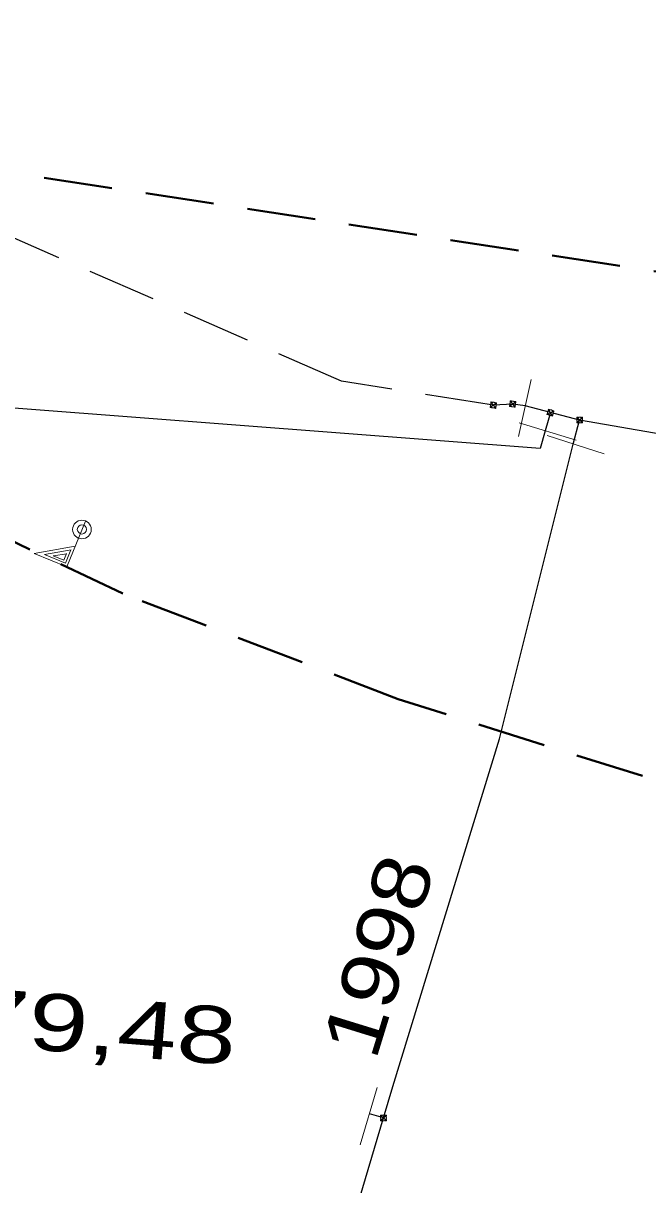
# Model space of a CAD drawing. Extents: x -740851 to -738888, y -1041382 to -1040235.
# Drawn here: x -739007.19 to -738996.26, y -1041347.67 to -1041327.35 of the extents above; entities that cross this region are included whole.
import ezdxf

# ---------------------------------------------------------------- set-up
doc = ezdxf.new("R2010")
doc.units = 0
doc.header["$LTSCALE"] = 0.4
doc.linetypes.add('MEDIUM_DASHED', pattern=[4.5, 3, -1.5])
doc.layers.add('18', color=7, linetype='Continuous', lineweight=13)
doc.layers.add('8', color=7, linetype='Continuous', lineweight=13)

msp = doc.modelspace()

# ---------------------------------------------------------------- linework, layer by layer
at = {"layer": '18', "linetype": 'MEDIUM_DASHED', "lineweight": 40}
msp.add_lwpolyline([(-738957.54, -1041347.45), (-738989.227, -1041342.273), (-738994.634, -1041341.058), (-739000.628, -1041339.172), (-739005.448, -1041337.328), (-739010.163, -1041335.083)], dxfattribs=at)
at = {"layer": '18'}
for points in [[(-739006.102, -1041336.058), (-739006.428, -1041336.858), (-739007, -1041336.626), (-739006.281, -1041336.497)], [(-739006.356, -1041336.56), (-739006.451, -1041336.794), (-739006.816, -1041336.645), (-739006.352, -1041336.562)], [(-739006.432, -1041336.627), (-739006.48, -1041336.744), (-739006.667, -1041336.668), (-739006.428, -1041336.629)]]:
    msp.add_lwpolyline(points, dxfattribs=at)
for centre, radius in [((-739006.163, -1041336.205), 0.163), ((-739006.163, -1041336.204), 0.0805)]:
    msp.add_circle(centre, radius, dxfattribs=at)
at = {"layer": '8'}
for p, q in [((-738998.517, -1041334.58), (-738998.3, -1041333.58)), ((-738999.016, -1041334.071), (-738998.902, -1041333.988)), ((-738999.001, -1041333.972), (-738999.004, -1041333.992)), ((-738999.001, -1041333.972), (-738998.917, -1041334.086)), ((-738999.001, -1041333.972), (-738998.981, -1041333.975)), ((-738998.902, -1041333.988), (-738998.922, -1041333.984)), ((-738998.902, -1041333.988), (-738998.905, -1041334.007)), ((-738998.565, -1041333.968), (-738998.677, -1041334.054)), ((-738998.664, -1041333.955), (-738998.667, -1041333.974)), ((-738998.578, -1041334.067), (-738998.664, -1041333.955)), ((-738998.664, -1041333.955), (-738998.644, -1041333.957)), ((-738998.565, -1041333.968), (-738998.585, -1041333.965)), ((-738998.565, -1041333.968), (-738998.568, -1041333.988)), ((-738999.016, -1041334.071), (-738999.013, -1041334.051)), ((-738999.016, -1041334.071), (-738998.996, -1041334.074)), ((-738998.917, -1041334.086), (-738998.937, -1041334.083)), ((-738998.917, -1041334.086), (-738998.914, -1041334.067)), ((-738998.677, -1041334.054), (-738998.675, -1041334.034)), ((-738998.677, -1041334.054), (-738998.658, -1041334.056)), ((-738998.578, -1041334.067), (-738998.598, -1041334.064)), ((-738998.578, -1041334.067), (-738998.576, -1041334.047)), ((-738997.898, -1041334.127), (-738998.021, -1041334.195)), ((-738998.021, -1041334.195), (-738998.016, -1041334.176)), ((-738998.021, -1041334.195), (-738998.002, -1041334.201)), ((-738997.994, -1041334.099), (-738997.999, -1041334.118)), ((-738997.994, -1041334.099), (-738997.925, -1041334.223)), ((-738997.994, -1041334.099), (-738997.975, -1041334.105)), ((-738997.925, -1041334.223), (-738997.92, -1041334.204)), ((-738997.898, -1041334.127), (-738997.917, -1041334.121)), ((-738997.898, -1041334.127), (-738997.903, -1041334.146)), ((-738997.51, -1041334.644), (-738998.51, -1041334.341)), ((-738997.925, -1041334.223), (-738997.944, -1041334.217)), ((-738997.498, -1041334.341), (-738997.398, -1041334.241)), ((-738997.498, -1041334.241), (-738997.398, -1041334.341)), ((-738997.498, -1041334.241), (-738997.498, -1041334.261)), ((-738997.498, -1041334.241), (-738997.478, -1041334.241)), ((-738997.498, -1041334.341), (-738997.498, -1041334.321)), ((-738997.498, -1041334.341), (-738997.478, -1041334.341)), ((-738997.398, -1041334.241), (-738997.418, -1041334.241)), ((-738997.398, -1041334.341), (-738997.418, -1041334.341)), ((-738997.398, -1041334.241), (-738997.398, -1041334.261)), ((-738997.398, -1041334.341), (-738997.398, -1041334.321)), ((-738997.02, -1041334.882), (-738998.02, -1041334.563)), ((-739001.291, -1041346.97), (-739000.994, -1041345.97)), ((-739000.933, -1041346.552), (-739000.833, -1041346.452)), ((-739000.933, -1041346.452), (-739000.833, -1041346.552)), ((-739000.933, -1041346.452), (-739000.933, -1041346.472)), ((-739000.933, -1041346.452), (-739000.913, -1041346.452)), ((-739000.933, -1041346.552), (-739000.933, -1041346.532)), ((-739000.933, -1041346.552), (-739000.913, -1041346.552)), ((-739000.833, -1041346.452), (-739000.853, -1041346.452)), ((-739000.833, -1041346.552), (-739000.853, -1041346.552)), ((-739000.833, -1041346.452), (-739000.833, -1041346.472)), ((-739000.833, -1041346.552), (-739000.833, -1041346.532))]:
    msp.add_line(p, q, dxfattribs=at)
at = {"layer": '8', "lineweight": 25}
for p, q in [((-738997.96, -1041334.16), (-738998.4, -1041334.04)), ((-738997.96, -1041334.16), (-738998.05, -1041334.48)), ((-738997.56, -1041334.71), (-738997.449, -1041334.292)), ((-739000.884, -1041346.503), (-739001.13, -1041346.43))]:
    msp.add_line(p, q, dxfattribs=at)
at = {"layer": '8', "linetype": 'MEDIUM_DASHED', "lineweight": 40}
msp.add_lwpolyline([(-739035.327, -1040869.176), (-739031.896, -1040886.019), (-739019.793, -1040911.158), (-738971.377, -1041006.096), (-738926.048, -1041090.986), (-738916.972, -1041110.384), (-738894.08, -1041157.618), (-738888.006, -1041177.327), (-738893.192, -1041219.807), (-738897.568, -1041245.006), (-738897.033, -1041287.959), (-738895.284, -1041302.914), (-738892.075, -1041339.057), (-738904.789, -1041346.08), (-738934.47, -1041341.14), (-739010.494, -1041329.487), (-739013.151, -1041330.629), (-739014.415, -1041331.172)], dxfattribs=at)
at = {"layer": '8', "linetype": 'MEDIUM_DASHED', "lineweight": 25}
msp.add_lwpolyline([(-738998.96, -1041334.03), (-739001.617, -1041333.611), (-739026.435, -1041322.774)], dxfattribs=at)
at = {"layer": '8', "lineweight": 25}
for points in [[(-738998.05, -1041334.48), (-738998.14, -1041334.79), (-739010.63, -1041333.83), (-739011.52, -1041335.25)], [(-738998.4, -1041334.04), (-738998.62, -1041334.01), (-738998.96, -1041334.03)], [(-738992.1, -1041335.22), (-738997.449, -1041334.292), (-738997.96, -1041334.16)], [(-739000.884, -1041346.503), (-739000.72, -1041345.95), (-738998.85, -1041339.87), (-738997.56, -1041334.71)], [(-739017.5, -1041382.24), (-739014.49, -1041375.96), (-739011.51, -1041371.98), (-739010.38, -1041370.12), (-739005.8, -1041363), (-739005.01, -1041360.4), (-739000.884, -1041346.503)]]:
    msp.add_lwpolyline(points, dxfattribs=at)
at = {"layer": '8'}
for points in [[(-738998.91, -1041334.037), (-738998.909, -1041334.032), (-738998.909, -1041334.027), (-738998.909, -1041334.022), (-738998.91, -1041334.017), (-738998.913, -1041334.011), (-738998.915, -1041334.007), (-738998.917, -1041334.002), (-738998.921, -1041333.998), (-738998.924, -1041333.994), (-738998.928, -1041333.991), (-738998.932, -1041333.987), (-738998.937, -1041333.984), (-738998.941, -1041333.982), (-738998.946, -1041333.981), (-738998.951, -1041333.98), (-738998.956, -1041333.979), (-738998.961, -1041333.979), (-738998.966, -1041333.979), (-738998.972, -1041333.981), (-738998.977, -1041333.983), (-738998.981, -1041333.985), (-738998.986, -1041333.987), (-738998.99, -1041333.991), (-738998.994, -1041333.994), (-738998.998, -1041333.998), (-738999.001, -1041334.002), (-738999.004, -1041334.007), (-738999.006, -1041334.012), (-738999.008, -1041334.016), (-738999.008, -1041334.021), (-738999.009, -1041334.026), (-738999.009, -1041334.031), (-738999.009, -1041334.037), (-738999.008, -1041334.042), (-738999.005, -1041334.047), (-738999.003, -1041334.052), (-738999.001, -1041334.056), (-738998.997, -1041334.061), (-738998.994, -1041334.064), (-738998.99, -1041334.068), (-738998.986, -1041334.071), (-738998.981, -1041334.074), (-738998.976, -1041334.076), (-738998.972, -1041334.078), (-738998.967, -1041334.079), (-738998.962, -1041334.079), (-738998.957, -1041334.079), (-738998.952, -1041334.079), (-738998.946, -1041334.078), (-738998.941, -1041334.076), (-738998.937, -1041334.073), (-738998.932, -1041334.071), (-738998.928, -1041334.068), (-738998.924, -1041334.064), (-738998.92, -1041334.061), (-738998.917, -1041334.056), (-738998.914, -1041334.051), (-738998.912, -1041334.047), (-738998.91, -1041334.042)], [(-738998.671, -1041334.004), (-738998.671, -1041334.009), (-738998.671, -1041334.014), (-738998.671, -1041334.019), (-738998.669, -1041334.024), (-738998.667, -1041334.03), (-738998.665, -1041334.034), (-738998.662, -1041334.039), (-738998.659, -1041334.043), (-738998.655, -1041334.047), (-738998.652, -1041334.05), (-738998.647, -1041334.054), (-738998.642, -1041334.056), (-738998.638, -1041334.058), (-738998.633, -1041334.06), (-738998.628, -1041334.06), (-738998.623, -1041334.061), (-738998.618, -1041334.061), (-738998.613, -1041334.06), (-738998.608, -1041334.059), (-738998.602, -1041334.057), (-738998.598, -1041334.054), (-738998.593, -1041334.052), (-738998.589, -1041334.049), (-738998.585, -1041334.045), (-738998.582, -1041334.041), (-738998.578, -1041334.037), (-738998.576, -1041334.032), (-738998.574, -1041334.027), (-738998.572, -1041334.023), (-738998.572, -1041334.018), (-738998.571, -1041334.013), (-738998.571, -1041334.008), (-738998.572, -1041334.002), (-738998.573, -1041333.997), (-738998.575, -1041333.992), (-738998.578, -1041333.988), (-738998.58, -1041333.983), (-738998.583, -1041333.979), (-738998.587, -1041333.975), (-738998.591, -1041333.972), (-738998.595, -1041333.968), (-738998.6, -1041333.965), (-738998.605, -1041333.964), (-738998.609, -1041333.962), (-738998.614, -1041333.961), (-738998.619, -1041333.961), (-738998.624, -1041333.961), (-738998.63, -1041333.961), (-738998.635, -1041333.963), (-738998.64, -1041333.965), (-738998.644, -1041333.967), (-738998.649, -1041333.97), (-738998.653, -1041333.973), (-738998.657, -1041333.977), (-738998.66, -1041333.98), (-738998.664, -1041333.985), (-738998.667, -1041333.99), (-738998.668, -1041333.994), (-738998.67, -1041333.999)], [(-738997.973, -1041334.209), (-738997.968, -1041334.21), (-738997.963, -1041334.211), (-738997.958, -1041334.211), (-738997.953, -1041334.211), (-738997.947, -1041334.209), (-738997.943, -1041334.207), (-738997.938, -1041334.206), (-738997.933, -1041334.203), (-738997.929, -1041334.2), (-738997.925, -1041334.197), (-738997.921, -1041334.193), (-738997.917, -1041334.189), (-738997.915, -1041334.184), (-738997.913, -1041334.18), (-738997.911, -1041334.175), (-738997.91, -1041334.17), (-738997.91, -1041334.165), (-738997.909, -1041334.16), (-738997.91, -1041334.154), (-738997.911, -1041334.149), (-738997.913, -1041334.144), (-738997.915, -1041334.139), (-738997.918, -1041334.135), (-738997.921, -1041334.131), (-738997.924, -1041334.127), (-738997.928, -1041334.122), (-738997.932, -1041334.119), (-738997.936, -1041334.117), (-738997.941, -1041334.114), (-738997.946, -1041334.113), (-738997.95, -1041334.112), (-738997.956, -1041334.111), (-738997.961, -1041334.111), (-738997.966, -1041334.111), (-738997.972, -1041334.113), (-738997.976, -1041334.115), (-738997.981, -1041334.116), (-738997.986, -1041334.119), (-738997.99, -1041334.122), (-738997.994, -1041334.125), (-738997.998, -1041334.129), (-738998.001, -1041334.133), (-738998.004, -1041334.138), (-738998.006, -1041334.142), (-738998.007, -1041334.147), (-738998.009, -1041334.152), (-738998.009, -1041334.157), (-738998.01, -1041334.162), (-738998.009, -1041334.168), (-738998.008, -1041334.173), (-738998.006, -1041334.178), (-738998.004, -1041334.183), (-738998.001, -1041334.188), (-738997.998, -1041334.192), (-738997.995, -1041334.196), (-738997.991, -1041334.2), (-738997.987, -1041334.203), (-738997.982, -1041334.205), (-738997.978, -1041334.208)], [(-738997.398, -1041334.291), (-738997.398, -1041334.286), (-738997.399, -1041334.281), (-738997.4, -1041334.276), (-738997.402, -1041334.271), (-738997.405, -1041334.266), (-738997.408, -1041334.262), (-738997.411, -1041334.258), (-738997.415, -1041334.254), (-738997.419, -1041334.251), (-738997.423, -1041334.248), (-738997.428, -1041334.245), (-738997.433, -1041334.243), (-738997.438, -1041334.242), (-738997.443, -1041334.241), (-738997.448, -1041334.241), (-738997.453, -1041334.241), (-738997.458, -1041334.242), (-738997.463, -1041334.243), (-738997.468, -1041334.245), (-738997.473, -1041334.248), (-738997.477, -1041334.251), (-738997.481, -1041334.254), (-738997.485, -1041334.258), (-738997.488, -1041334.262), (-738997.491, -1041334.266), (-738997.494, -1041334.271), (-738997.496, -1041334.276), (-738997.497, -1041334.281), (-738997.498, -1041334.286), (-738997.498, -1041334.291), (-738997.498, -1041334.296), (-738997.497, -1041334.301), (-738997.496, -1041334.306), (-738997.494, -1041334.311), (-738997.491, -1041334.316), (-738997.488, -1041334.32), (-738997.485, -1041334.324), (-738997.481, -1041334.328), (-738997.477, -1041334.331), (-738997.473, -1041334.334), (-738997.468, -1041334.337), (-738997.463, -1041334.339), (-738997.458, -1041334.34), (-738997.453, -1041334.341), (-738997.448, -1041334.341), (-738997.443, -1041334.341), (-738997.438, -1041334.34), (-738997.433, -1041334.339), (-738997.428, -1041334.337), (-738997.423, -1041334.334), (-738997.419, -1041334.331), (-738997.415, -1041334.328), (-738997.411, -1041334.324), (-738997.408, -1041334.32), (-738997.405, -1041334.316), (-738997.402, -1041334.311), (-738997.4, -1041334.306), (-738997.399, -1041334.301), (-738997.398, -1041334.296)], [(-739000.833, -1041346.502), (-739000.833, -1041346.497), (-739000.834, -1041346.492), (-739000.835, -1041346.487), (-739000.837, -1041346.482), (-739000.84, -1041346.477), (-739000.843, -1041346.473), (-739000.846, -1041346.469), (-739000.85, -1041346.465), (-739000.854, -1041346.462), (-739000.858, -1041346.459), (-739000.863, -1041346.456), (-739000.868, -1041346.454), (-739000.873, -1041346.453), (-739000.878, -1041346.452), (-739000.883, -1041346.452), (-739000.888, -1041346.452), (-739000.893, -1041346.453), (-739000.898, -1041346.454), (-739000.903, -1041346.456), (-739000.908, -1041346.459), (-739000.912, -1041346.462), (-739000.916, -1041346.465), (-739000.92, -1041346.469), (-739000.923, -1041346.473), (-739000.926, -1041346.477), (-739000.929, -1041346.482), (-739000.931, -1041346.487), (-739000.932, -1041346.492), (-739000.933, -1041346.497), (-739000.933, -1041346.502), (-739000.933, -1041346.507), (-739000.932, -1041346.512), (-739000.931, -1041346.517), (-739000.929, -1041346.522), (-739000.926, -1041346.527), (-739000.923, -1041346.531), (-739000.92, -1041346.535), (-739000.916, -1041346.539), (-739000.912, -1041346.542), (-739000.908, -1041346.545), (-739000.903, -1041346.548), (-739000.898, -1041346.55), (-739000.893, -1041346.551), (-739000.888, -1041346.552), (-739000.883, -1041346.552), (-739000.878, -1041346.552), (-739000.873, -1041346.551), (-739000.868, -1041346.55), (-739000.863, -1041346.548), (-739000.858, -1041346.545), (-739000.854, -1041346.542), (-739000.85, -1041346.539), (-739000.846, -1041346.535), (-739000.843, -1041346.531), (-739000.84, -1041346.527), (-739000.837, -1041346.522), (-739000.835, -1041346.517), (-739000.834, -1041346.512), (-739000.833, -1041346.507)]]:
    msp.add_lwpolyline(points, close=True, dxfattribs=at)

# ---------------------------------------------------------------- texts
at = {"layer": '18', "width": 1.4}
msp.add_text('179,48', height=1, rotation=355.55, dxfattribs=at).set_placement((-739009.206, -1041345.134))
at = {"layer": '8', "width": 1.2}
msp.add_text('1998', height=1, rotation=72.904, dxfattribs=at).set_placement((-739001.022, -1041345.519))

doc.saveas('drawing.dxf')
